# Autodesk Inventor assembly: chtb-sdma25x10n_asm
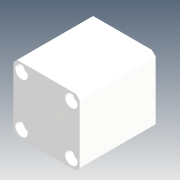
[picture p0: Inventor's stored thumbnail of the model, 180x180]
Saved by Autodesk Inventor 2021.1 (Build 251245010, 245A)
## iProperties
Company: Microsoft
Created: 2018-05
Part Number: chtb-sdma25x10n_asm
Description: STEP AP214
Document SubType Name: Assembly
Designer: user
Title: chtb-sdma25x10n_asm.STEP
Author: Windows
Revision Number: ÈÎºÎ
Sending System: SolidWorks 2015
Preprocessor: SwSTEP 2.0
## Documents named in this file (4)
- D:\Vault_2016\Projekty\Clamptek\Hydraulic\CHTB\CHTB-25\Inventor\chtb-sdma25x10n\chtb-sdma25x10n_asm.iam
- D:\Vault_2016\Projekty\Clamptek\Hydraulic\CHTB\CHTB-25\Inventor\chtb-sdma25x10n\CHTB-25QG.ipt
- D:\Vault_2016\Projekty\Clamptek\Hydraulic\CHTB\CHTB-25\Inventor\chtb-sdma25x10n\CHTB-SDMA25X10NBT.ipt
- D:\Vault_2016\Projekty\Clamptek\Hydraulic\CHTB\CHTB-25\Inventor\chtb-sdma25x10n\CHTB-SDMA25X10NHSG.ipt
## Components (3 placed, 3 different names)
1. CHTB-25QG_1
2. CHTB-SDMA25X10NBT_2
3. CHTB-SDMA25X10NHSG_3
